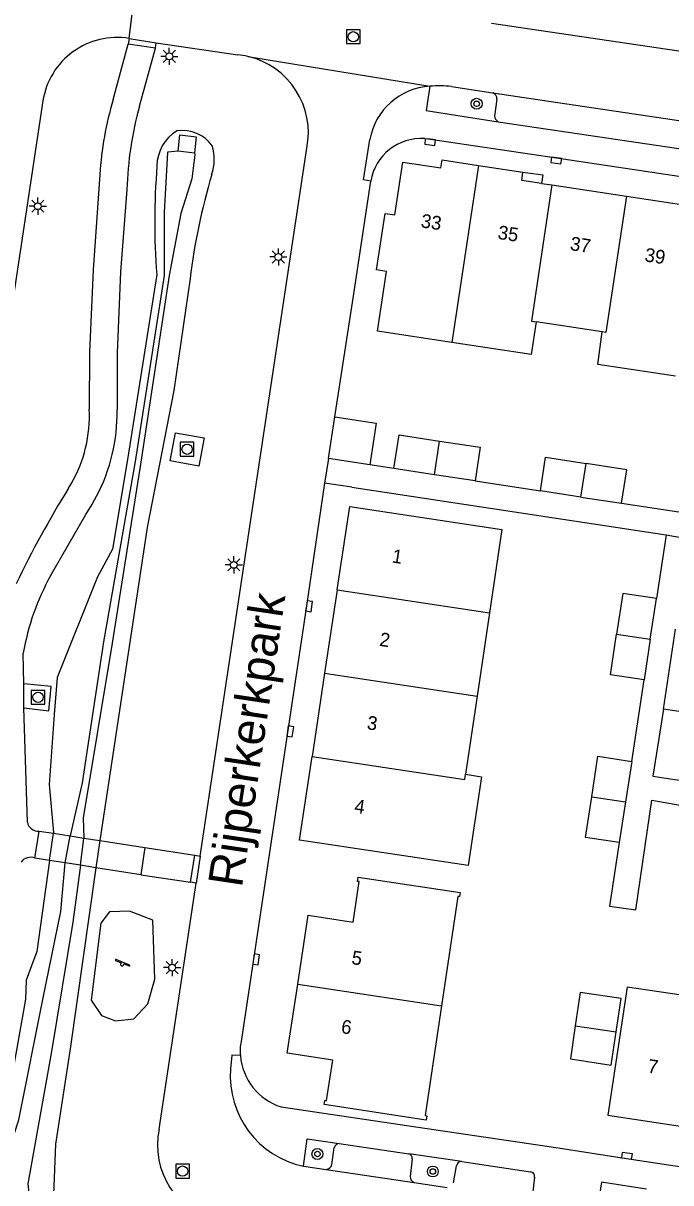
# Model space of a CAD drawing. Extents: x 124000 to 128010, y 398999 to 403000.
# Drawn here: x 126438.8 to 126486, y 399996.7 to 400081.2 of the extents above; entities that cross this region are included whole.
import ezdxf

# ---------------------------------------------------------------- set-up
doc = ezdxf.new("R2010")
doc.units = 0
for name, color, linetype in [('gg-afsc-hekwerk', 7, 'Continuous'), ('gg-anno-huisnummerreeks BGT', 7, 'Continuous'), ('gg-anno-openbare ruimte label', 7, 'Continuous'), ('gg-bbg-bijgebouw', 7, 'Continuous'), ('gg-bbg-hoofdgebouw', 7, 'Continuous'), ('gg-bbg-luifel en loopbrug', 7, 'Continuous'), ('gg-bbg-onder overbouw', 7, 'Continuous'), ('gg-bbg-pand overbouw', 7, 'Continuous'), ('gg-bbg-tussenscheiding', 7, 'Continuous'), ('gg-knt-bovenkant onderkant talud', 7, 'Continuous'), ('gg-knt-onverhard', 7, 'Continuous'), ('gg-knt-verharding', 7, 'Continuous'), ('gg-knt-verharding nz', 7, 'Continuous'), ('gg-kntw-wadi', 7, 'Continuous'), ('gg-kwrk-kunstwerk niveau 01', 7, 'Continuous'), ('gg-kwrk-uitstroombak niveau min 01', 7, 'Continuous'), ('gt-grn-weggrens', 7, 'Continuous'), ('gt-symb-boom', 7, 'Continuous'), ('gt-symb-kolk', 7, 'Continuous'), ('gt-symb-lichtmast', 7, 'Continuous'), ('gt-symb-rioolschacht', 7, 'Continuous'), ('gt-symb-speelvoorziening', 7, 'Continuous'), ('gt-symb-talud symbool', 7, 'Continuous')]:
    doc.layers.add(name, color=color, linetype=linetype)

# ---------------------------------------------------------------- blocks, each defined once
blk = doc.blocks.new('gt0-KOLK')
at = {"layer": 'gt-symb-kolk'}
blk.add_lwpolyline([(0, 0), (0.375, 0), (0.375, 0.4), (-0.375, 0.4), (-0.375, 0), (0, 0)], dxfattribs=at)
blk = doc.blocks.new('gt0-RS')
at = {"layer": 'gt-symb-rioolschacht'}
blk.add_lwpolyline([(-0.5, -0.5), (0.5, -0.5), (0.5, 0.5), (-0.5, 0.5)], close=True, dxfattribs=at)
blk.add_circle((0, 0), 0.375, dxfattribs=at)
blk = doc.blocks.new('gt0-BOOM')
at = {"layer": 'gt-symb-boom'}
for radius in [0.4, 0.2]:
    blk.add_circle((0, 0), radius, dxfattribs=at)
blk = doc.blocks.new('gt0-LMAST')
at = {"layer": 'gt-symb-lichtmast'}
for p, q in [((-0.182, 0.173), (-0.447, 0.438)), ((-0.005, 0.246), (-0.005, 0.621)), ((0.172, 0.173), (0.437, 0.438)), ((-0.255, -0.004), (-0.63, -0.004)), ((-0.182, -0.181), (-0.447, -0.446)), ((-0.005, -0.254), (-0.005, -0.629)), ((0.437, -0.446), (0.172, -0.181)), ((0.245, -0.004), (0.62, -0.004))]:
    blk.add_line(p, q, dxfattribs=at)
blk.add_circle((-0.005, -0.004), 0.25, dxfattribs=at)
blk = doc.blocks.new('gt0-TALUD_1')
at = {"layer": 'gt-symb-talud symbool'}
for p, q in [((-1, -1), (-1, 0)), ((0, -1), (0, 0)), ((0, -2), (0, 0)), ((0, -2), (0, 0)), ((1, -1), (1, 0))]:
    blk.add_line(p, q, dxfattribs=at)
blk = doc.blocks.new('gt0-SV')
at = {"layer": 'gt-symb-speelvoorziening'}
for p, q in [((-0.477, 0.255), (-0.08, 0.096)), ((0.542, -0.076), (-0.449, 0.324)), ((0.125, 0.014), (0.515, -0.143))]:
    blk.add_line(p, q, dxfattribs=at)
for centre, radius, start, end in [((-0.466, 0.291), 0.0369, 63.6251, 252.66016), ((-0.002, -0.005), 0.128, 127.68665, 8.59861), ((0.531, -0.111), 0.0363, 243.50852, 72.54358)]:
    blk.add_arc(centre, radius, start, end, dxfattribs=at)

msp = doc.modelspace()

# ---------------------------------------------------------------- linework, layer by layer
at = {"layer": 'gg-afsc-hekwerk'}
for p, q in [((126461.49, 400052.473), (126462.878, 400061.437)), ((126465.807, 400048.704), (126464.049, 400048.977)), ((126471.72, 400047.809), (126476.486, 400047.087)), ((126462.732, 400047.344), (126485.652, 400043.878)), ((126482.399, 400046.18), (126487.702, 400045.388)), ((126485.652, 400043.878), (126484.949, 400039.234)), ((126483.142, 400027.377), (126484.039, 400033.304)), ((126468.052, 400000.658), (126477.773, 399999.209))]:
    msp.add_line(p, q, dxfattribs=at)
msp.add_lwpolyline([(126482.238, 400021.463), (126481.534, 400016.836), (126483.432, 400016.548), (126484.616, 400024.559), (126487.494, 400024.031)], dxfattribs=at)
at = {"layer": 'gg-bbg-bijgebouw'}
for p, q in [((126468.764, 400048.256), (126465.807, 400048.704)), ((126471.72, 400047.809), (126468.764, 400048.256)), ((126479.443, 400046.633), (126476.486, 400047.087)), ((126479.443, 400046.633), (126482.399, 400046.18)), ((126484.494, 400036.269), (126484.949, 400039.234)), ((126484.494, 400036.269), (126484.039, 400033.304)), ((126483.142, 400027.377), (126482.69, 400024.42)), ((126482.69, 400024.42), (126482.238, 400021.463)), ((126482.009, 400007.669), (126482.371, 400010.089))]:
    msp.add_line(p, q, dxfattribs=at)
for points in [[(126465.807, 400048.704), (126466.183, 400051.165), (126469.139, 400050.713)], [(126469.139, 400050.713), (126472.095, 400050.26), (126471.72, 400047.809)], [(126476.486, 400047.087), (126476.862, 400049.535), (126479.821, 400049.081)], [(126482.399, 400046.18), (126482.779, 400048.627), (126479.821, 400049.081)], [(126484.949, 400039.234), (126482.495, 400039.611), (126482.041, 400036.65)], [(126484.039, 400033.304), (126481.586, 400033.689), (126482.041, 400036.65)], [(126480.233, 400024.796), (126480.682, 400027.753), (126483.142, 400027.377)], [(126482.238, 400021.463), (126479.784, 400021.838), (126480.233, 400024.796)], [(126482.371, 400010.089), (126479.386, 400010.536), (126479.028, 400008.115)], [(126479.028, 400008.115), (126478.67, 400005.694), (126481.646, 400005.248), (126482.009, 400007.669)]]:
    msp.add_lwpolyline(points, dxfattribs=at)
at = {"layer": 'gg-bbg-hoofdgebouw'}
for p, q in [((126471.98, 400070.794), (126475.215, 400070.307)), ((126476.575, 400069.487), (126477.326, 400069.374)), ((126477.326, 400069.374), (126482.762, 400068.554)), ((126482.762, 400068.554), (126488.198, 400067.734)), ((126480.999, 400058.658), (126476.178, 400059.392)), ((126461.664, 400039.866), (126460.75, 400033.793)), ((126472.773, 400038.194), (126471.873, 400032.119)), ((126460.75, 400033.793), (126459.836, 400027.719)), ((126471.873, 400032.119), (126471.033, 400026.444))]:
    msp.add_line(p, q, dxfattribs=at)
for points in [[(126470.029, 400057.891), (126464.595, 400058.706), (126465.267, 400063.074), (126464.535, 400063.184), (126465.157, 400067.302), (126465.879, 400067.186), (126466.455, 400071.027), (126469.23, 400070.61), (126469.313, 400071.195), (126471.98, 400070.794)], [(126476.178, 400059.392), (126475.81, 400057.023), (126470.029, 400057.891)], [(126486.339, 400055.435), (126480.665, 400056.283), (126480.999, 400058.658)], [(126461.664, 400039.866), (126462.578, 400045.939), (126473.671, 400044.261), (126472.773, 400038.194)], [(126471.033, 400026.444), (126472.188, 400026.259), (126471.215, 400019.788), (126458.922, 400021.646), (126459.836, 400027.719)], [(126458.792, 400011.136), (126459.552, 400016.163), (126462.821, 400015.668), (126463.266, 400018.612), (126463.149, 400018.63), (126463.198, 400018.947), (126470.643, 400017.828), (126470.593, 400017.521), (126470.475, 400017.54), (126469.283, 400009.553)], [(126469.283, 400009.553), (126468.091, 400001.566), (126468.21, 400001.548), (126468.163, 400001.242), (126460.71, 400002.366), (126460.759, 400002.676), (126460.897, 400002.657), (126461.343, 400005.607), (126458.031, 400006.108), (126458.792, 400011.136)], [(126488.251, 400010.111), (126482.822, 400010.928), (126481.406, 400001.594), (126486.84, 400000.781)]]:
    msp.add_lwpolyline(points, dxfattribs=at)
at = {"layer": 'gg-bbg-luifel en loopbrug'}
for p, q in [((126461.022, 400049.448), (126461.49, 400052.473)), ((126464.049, 400048.977), (126461.022, 400049.448))]:
    msp.add_line(p, q, dxfattribs=at)
msp.add_lwpolyline([(126461.49, 400052.473), (126464.517, 400052.004), (126464.049, 400048.977)], dxfattribs=at)
at = {"layer": 'gg-bbg-onder overbouw'}
msp.add_lwpolyline([(126476.575, 400069.487), (126475.12, 400069.706), (126475.215, 400070.307)], dxfattribs=at)
at = {"layer": 'gg-bbg-pand overbouw'}
msp.add_lwpolyline([(126475.215, 400070.307), (126476.666, 400070.097), (126476.575, 400069.487)], dxfattribs=at)
at = {"layer": 'gg-bbg-tussenscheiding'}
for p, q in [((126471.98, 400070.794), (126470.029, 400057.891)), ((126468.764, 400048.256), (126469.139, 400050.713)), ((126479.443, 400046.633), (126479.821, 400049.081)), ((126461.664, 400039.866), (126472.773, 400038.194)), ((126482.041, 400036.65), (126484.494, 400036.269)), ((126460.75, 400033.793), (126471.873, 400032.119)), ((126480.233, 400024.796), (126482.69, 400024.42)), ((126458.792, 400011.136), (126469.283, 400009.553)), ((126479.028, 400008.115), (126482.009, 400007.669))]:
    msp.add_line(p, q, dxfattribs=at)
for points in [[(126477.326, 400069.374), (126475.824, 400059.446), (126476.178, 400059.392)], [(126482.762, 400068.554), (126481.26, 400058.618), (126480.999, 400058.658)], [(126459.836, 400027.719), (126470.973, 400026.043), (126471.033, 400026.444)]]:
    msp.add_lwpolyline(points, dxfattribs=at)
at = {"layer": 'gg-knt-bovenkant onderkant talud'}
for p, q in [((126441.843, 400019.975), (126442.197, 400021.943)), ((126442.946, 400019.804), (126443.187, 400021.788))]:
    msp.add_line(p, q, dxfattribs=at)
for points in [[(126450.065, 400071.827), (126449.29, 400071.769), (126449.041, 400067.362), (126449.054, 400062.763), (126446.939, 400049.215), (126444.631, 400036.083), (126443.062, 400025.807), (126442.197, 400021.943)], [(126451.253, 400071.688), (126451.295, 400071.553), (126451.073, 400069.82), (126450.26, 400067.3), (126449.421, 400062.781), (126447.346, 400049.163), (126445.257, 400035.977), (126443.146, 400023.27), (126443.187, 400021.788)], [(126437.038, 399976.312), (126439.455, 399977.35), (126439.966, 399980.169), (126437.418, 399984.342), (126436.681, 399987.951), (126436.785, 399989.799), (126436.183, 399993.081), (126436.787, 399996.183), (126438.458, 400001.253), (126440.236, 400010.137), (126441.529, 400016.438), (126441.843, 400019.975)], [(126442.946, 400019.804), (126442.387, 400015.672), (126440.846, 400006.228), (126439.119, 399996.608), (126439.452, 399993.471), (126440.93, 399988.822), (126444.234, 399983.238), (126448.631, 399977.392), (126450.459, 399973.821), (126451.195, 399973.096)]]:
    msp.add_lwpolyline(points, dxfattribs=at)
at = {"layer": 'gg-knt-onverhard'}
msp.add_lwpolyline([(126443.724, 400009.981), (126444.477, 400008.859), (126445.502, 400008.461), (126446.838, 400008.611), (126447.853, 400009.71), (126448.367, 400011.497), (126448.233, 400015.813), (126446.534, 400016.457), (126445.07, 400016.42), (126444.427, 400015.586), (126443.724, 400009.981)], dxfattribs=at)
at = {"layer": 'gg-knt-verharding'}
for p, q in [((126472.908, 400081.167), (126559.26, 400068.335)), ((126446.493, 400080.041), (126446.437, 400079.627)), ((126445.33, 400075.589), (126446.437, 400079.627)), ((126448.421, 400079.336), (126446.437, 400079.627)), ((126447.241, 400075.12), (126448.421, 400079.336)), ((126448.421, 400079.336), (126448.474, 400079.729)), ((126448.474, 400079.729), (126454.421, 400078.852)), ((126469.997, 400076.534), (126473.009, 400076.084)), ((126440.207, 400075.487), (126434.503, 400037.804)), ((126473.319, 400075.627), (126473.146, 400074.393)), ((126473.397, 400073.977), (126495.254, 400070.727)), ((126463.596, 400069.732), (126464.041, 400072.686)), ((126451.674, 400020.479), (126459.446, 400072.04)), ((126462.878, 400061.437), (126464.11, 400069.634)), ((126461.022, 400049.448), (126460.752, 400047.639)), ((126442.087, 400047.28), (126442.276, 400047.595)), ((126462.732, 400047.344), (126460.752, 400047.639)), ((126438.816, 400033.022), (126438.781, 400035.255)), ((126438.821, 400031.267), (126438.816, 400033.022)), ((126439.075, 400022.936), (126438.821, 400031.267)), ((126447.636, 400021.088), (126451.279, 400020.539)), ((126450.982, 400018.571), (126451.279, 400020.539)), ((126451.279, 400020.539), (126451.674, 400020.479)), ((126447.343, 400019.12), (126450.982, 400018.571)), ((126448.676, 400000.587), (126451.378, 400018.511)), ((126451.378, 400018.511), (126450.982, 400018.571)), ((126453.985, 400005.978), (126453.891, 400004.975)), ((126457.574, 400002.202), (126468.052, 400000.658)), ((126461.274, 399997.993), (126461.442, 399999.23)), ((126461.821, 399999.542), (126466.884, 399998.771)), ((126470.757, 399998.22), (126466.884, 399998.771)), ((126467.146, 399998.415), (126466.983, 399997.12)), ((126470.757, 399998.22), (126475.765, 399997.473)), ((126459.203, 399997.881), (126460.874, 399997.651)), ((126470.148, 399996.671), (126470.361, 399997.902)), ((126467.273, 399996.702), (126469.694, 399996.334)), ((126476.054, 399997.07), (126475.9, 399995.824))]:
    msp.add_line(p, q, dxfattribs=at)
for points in [[(126468.425, 400076.565), (126468.156, 400074.785), (126473.397, 400073.977)], [(126468.047, 400072.746), (126468.466, 400072.696), (126477.668, 400071.349), (126487.059, 400069.944), (126497.726, 400068.361), (126521.179, 400064.893), (126532.133, 400063.261), (126533.748, 400062.999)], [(126444.353, 400070.14), (126443.882, 400063.195), (126443.599, 400057.189), (126443.593, 400053.044)], [(126446.327, 400069.03), (126445.878, 400063.036), (126445.631, 400057.136), (126445.619, 400052.975)], [(126449.489, 400049.259), (126449.883, 400051.318), (126451.964, 400050.948), (126451.57, 400048.889), (126449.489, 400049.259)], [(126460.752, 400047.639), (126459.42, 400038.711), (126454.657, 400006.978)], [(126440.754, 400040.882), (126443.342, 400045.37), (126443.776, 400046.053), (126444.129, 400046.687)], [(126438.821, 400031.267), (126440.63, 400031.068), (126440.812, 400032.825), (126438.816, 400033.022)], [(126459.203, 399997.881), (126459.468, 399999.869), (126461.821, 399999.542)], [(126477.773, 399999.209), (126482.763, 399998.438), (126504.041, 399995.245), (126513.61, 399993.796)], [(126484.224, 399996.2), (126480.931, 399996.709), (126480.631, 399994.701)]]:
    msp.add_lwpolyline(points, dxfattribs=at)
for centre, radius, start, end in [((126445.611, 400074.642), 5.47, 80.7257, 171.11849), ((126453.864, 400073.149), 5.73, 77.03368, 84.42424), ((126453.87, 400073.186), 5.693, 348.38597, 77.00397), ((126468.729, 400071.804), 4.77, 93.65686, 169.34848), ((126469.065, 400069.131), 7.461, 82.82216, 94.91837), ((126472.875, 400075.659), 0.445, 355.81679, 72.4842), ((126470.065, 400068.342), 25.775, 163.67014, 175.99973), ((126473.67, 400068.04), 27.361, 165.00316, 177.9261), ((126473.651, 400074.414), 0.506, 182.38744, 239.82321), ((126467.799, 400069.013), 3.741, 86.20287, 170.44631), ((126433.643, 400052.565), 9.961, 330.06988, 2.75499), ((126432.47, 400052.77), 13.151, 332.44601, 0.89221), ((126500.31, 400010.806), 68.704, 147.93482, 154.57296), ((126456.567, 400032.178), 18.051, 151.17055, 170.18497), ((126439.851, 400023.087), 0.791, 190.989, 275.78699), ((126439.302, 400019.554), 0.832, 67.07041, 144.24387), ((126458.014, 400006.301), 3.425, 168.59206, 186.14307), ((126458.885, 400006.287), 4.29, 184.72024, 252.21265), ((126460.592, 400004.457), 6.721, 175.57563, 258.07624), ((126454.334, 399999.435), 5.774, 168.49572, 256.31279), ((126461.908, 399999.05), 0.499, 100.02254, 158.90118), ((126460.866, 399998.065), 0.414, 271.07296, 349.98792), ((126466.811, 399998.443), 0.336, 355.18143, 77.52137), ((126470.723, 399997.856), 0.365, 84.69314, 172.8379), ((126467.427, 399997.118), 0.444, 179.75378, 249.75049), ((126475.728, 399997.141), 0.334, 347.67507, 83.61518)]:
    msp.add_arc(centre, radius, start, end, dxfattribs=at)
at = {"layer": 'gg-knt-verharding nz'}
for p, q in [((126446.493, 400080.041), (126448.474, 400079.729)), ((126473.009, 400076.084), (126496.285, 400072.603)), ((126464.11, 400069.634), (126463.596, 400069.732)), ((126485.456, 400031.187), (126486.336, 400037.006)), ((126502.773, 400028.535), (126485.456, 400031.187)), ((126451.674, 400020.479), (126451.378, 400018.511)), ((126454.609, 400005.934), (126453.985, 400005.978)), ((126460.874, 399997.651), (126467.273, 399996.702))]:
    msp.add_line(p, q, dxfattribs=at)
msp.add_lwpolyline([(126485.456, 400031.187), (126484.692, 400026.305), (126502.03, 400023.679), (126502.773, 400028.535)], dxfattribs=at)
at = {"layer": 'gg-kntw-wadi'}
for p, q in [((126440.693, 400020.154), (126440.976, 400022.136)), ((126444.35, 400021.605), (126444.081, 400019.627))]:
    msp.add_line(p, q, dxfattribs=at)
for points in [[(126448.512, 400062.839), (126446.369, 400049.362), (126445.275, 400042.845), (126444.189, 400040.811), (126441.242, 400033.484), (126441.029, 400030.78), (126440.673, 400025.696), (126440.985, 400022.201), (126440.976, 400022.136)], [(126450.935, 400062.545), (126449.768, 400054.385), (126447.814, 400044.403), (126444.35, 400021.605)], [(126440.693, 400020.154), (126439.765, 400013.535), (126438.978, 400011.432), (126438.951, 400010.052), (126437.96, 400004.551), (126436.93, 400001.475), (126435.402, 399997.942), (126434.618, 399993.56), (126434.425, 399988.64), (126435.126, 399984.95), (126436.768, 399980.353), (126437.02, 399979.222), (126436.765, 399978.342), (126435.749, 399978.042)], [(126444.081, 400019.627), (126442.206, 400006.439), (126441.121, 399999.496), (126440.988, 399995.81), (126441.638, 399993.639), (126443.627, 399991.225), (126443.659, 399989.15), (126450.528, 399981.777), (126452.965, 399978.149), (126453.59, 399976.129), (126453.33, 399974.96)]]:
    msp.add_lwpolyline(points, dxfattribs=at)
for centre, radius, start, end in [((126451.487, 400070.76), 2.959, 120.34734, 180.18216), ((126450.386, 400070.685), 2.659, 34.77295, 98.52443), ((126449.394, 400071.247), 3.316, 340.24125, 16.72209), ((126497.653, 400066.696), 49.292, 175.28084, 184.48743), ((126498.923, 400056.499), 48.367, 163.63557, 172.81879)]:
    msp.add_arc(centre, radius, start, end, dxfattribs=at)
at = {"layer": 'gg-kwrk-kunstwerk niveau 01'}
for p, q in [((126439.626, 400020.32), (126439.931, 400022.3)), ((126439.931, 400022.3), (126440.976, 400022.136)), ((126440.976, 400022.136), (126442.197, 400021.943)), ((126442.197, 400021.943), (126443.187, 400021.788)), ((126443.187, 400021.788), (126444.35, 400021.605)), ((126444.35, 400021.605), (126447.636, 400021.088)), ((126447.636, 400021.088), (126447.343, 400019.12)), ((126440.693, 400020.154), (126439.626, 400020.32)), ((126441.843, 400019.975), (126440.693, 400020.154)), ((126442.946, 400019.804), (126441.843, 400019.975)), ((126444.081, 400019.627), (126442.946, 400019.804)), ((126447.343, 400019.12), (126444.081, 400019.627))]:
    msp.add_line(p, q, dxfattribs=at)
at = {"layer": 'gg-kwrk-uitstroombak niveau min 01'}
msp.add_line((126451.253, 400071.688), (126450.065, 400071.827), dxfattribs=at)
msp.add_lwpolyline([(126450.065, 400071.827), (126450.203, 400073.019), (126451.392, 400072.88), (126451.253, 400071.688)], dxfattribs=at)
at = {"layer": 'gt-grn-weggrens'}
for p, q in [((126446.493, 400080.041), (126447.099, 400084.971)), ((126455.15, 400078.733), (126468.425, 400076.565)), ((126485.652, 400043.878), (126487.43, 400043.57))]:
    msp.add_line(p, q, dxfattribs=at)

# ---------------------------------------------------------------- block references
at = {"layer": 'gt-symb-boom'}
for p in [(126471.835, 400075.284), (126460.227, 399998.767), (126468.641, 399997.495)]:
    msp.add_blockref('gt0-BOOM', p, dxfattribs=at)
at = {"layer": 'gt-symb-kolk'}
for p, rotation in [((126468.466, 400072.696), 173.08318906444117), ((126477.668, 400071.349), 171.6747391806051), ((126459.42, 400038.711), -98.54552999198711), ((126458.049, 400029.588), -98.52039143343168), ((126455.561, 400012.978), -98.56149019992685), ((126482.763, 399998.438), -8.537549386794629)]:
    msp.add_blockref('gt0-KOLK', p, dxfattribs=dict(at, rotation=rotation))
at = {"layer": 'gt-symb-lichtmast'}
for p in [(126449.433, 400078.742), (126439.841, 400067.828), (126457.384, 400064.127), (126454.134, 400041.694), (126449.638, 400012.354)]:
    msp.add_blockref('gt0-LMAST', p, dxfattribs=at)
at = {"layer": 'gt-symb-rioolschacht'}
for p in [(126462.843, 400080.165), (126450.725, 400050.119), (126439.857, 400032.041), (126450.398, 399997.521)]:
    msp.add_blockref('gt0-RS', p, dxfattribs=at)
at = {"layer": 'gt-symb-speelvoorziening'}
msp.add_blockref('gt0-SV', (126445.991, 400012.611), dxfattribs=at)
at = {"layer": 'gt-symb-talud symbool', "xscale": 0.001, "yscale": 0.001, "rotation": 90}
msp.add_blockref('gt0-TALUD_1', (126447.513, 400056.645), dxfattribs=at)

# ---------------------------------------------------------------- texts
at = {"layer": 'gg-anno-huisnummerreeks BGT'}
for s, rotation, p in [('33', 351.5, (126467.724, 400066.286)), ('35', 351.4, (126473.332, 400065.447)), ('37', 351.4, (126478.604, 400064.631)), ('39', 351.4, (126484.04, 400063.811)), ('1', 351.4, (126465.618, 400041.871)), ('2', 351.4, (126464.704, 400035.798)), ('3', 351.4, (126463.79, 400029.725)), ('4', 351.4, (126462.876, 400023.651)), ('5', 351.4, (126462.668, 400012.616)), ('6', 351.4, (126461.907, 400007.587)), ('7', 351.5, (126484.257, 400004.706))]:
    msp.add_text(s, height=1, rotation=rotation, dxfattribs=at).set_placement(p)
at = {"layer": 'gg-anno-openbare ruimte label'}
msp.add_text('Rijperkerkpark', height=2.5, rotation=81.5, dxfattribs=at).set_placement((126454.714, 400018.125))

doc.saveas('drawing.dxf')
